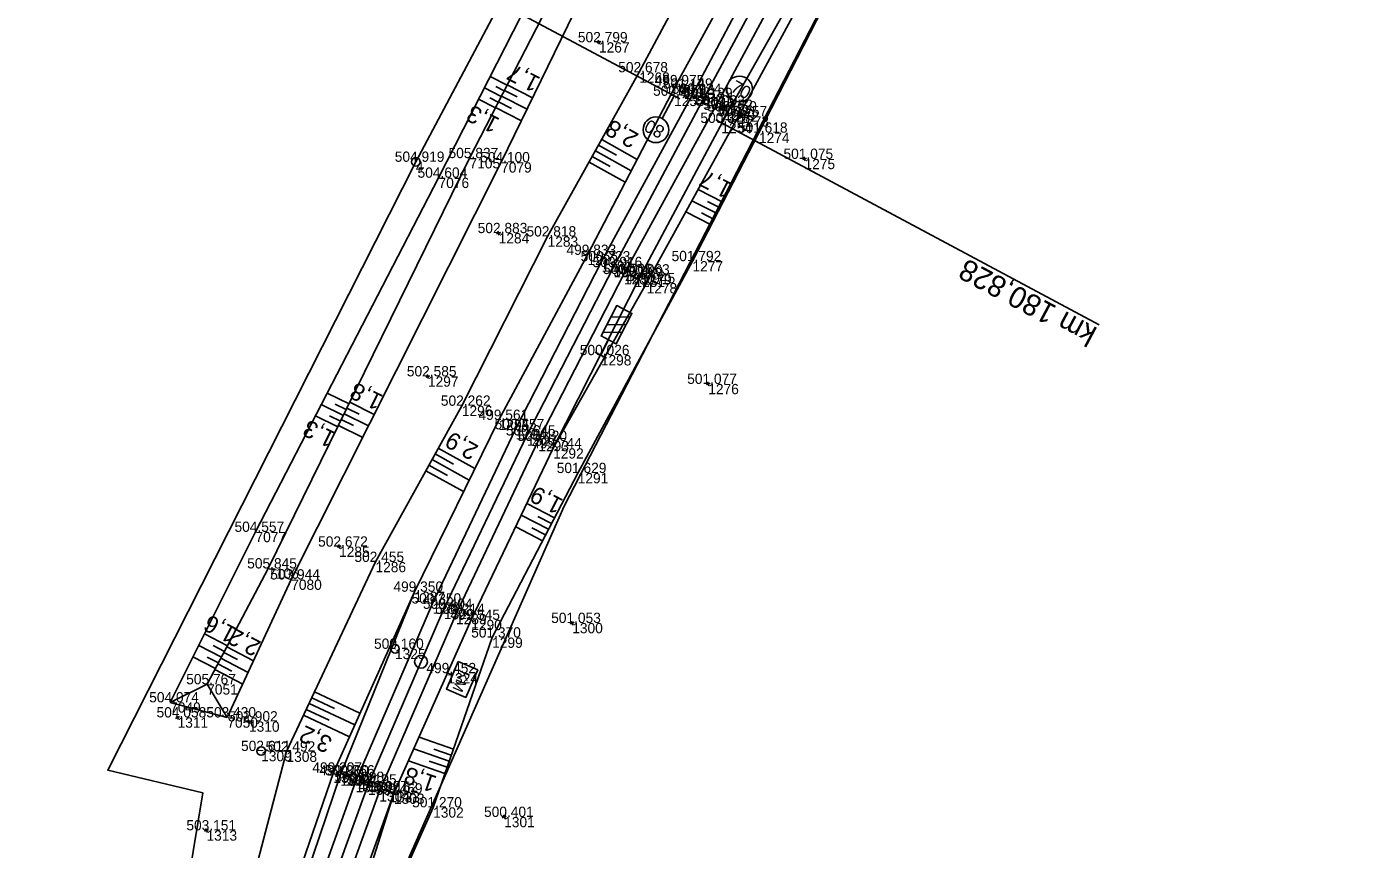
# Model space of a CAD drawing. Extents: x -1234191 to 23050, y -1290331 to -741191.
# Drawn here: x -865301.6 to -865146.4, y -1106697.5 to -1106601.4 of the extents above; entities that cross this region are included whole.
import ezdxf

# ---------------------------------------------------------------- set-up
doc = ezdxf.new("R2010")
doc.units = 0
for name, color, linetype in [('Vrstva 1', 7, 'Continuous'), ('Vrstva 36', 7, 'Continuous'), ('Vrstva 4', 7, 'Continuous'), ('Vrstva 48', 7, 'Continuous'), ('Vrstva 49', 7, 'Continuous'), ('Vrstva 5', 7, 'Continuous'), ('Vrstva 53', 7, 'Continuous'), ('Vrstva 60', 7, 'Continuous'), ('Vrstva 61', 7, 'Continuous'), ('Vrstva 7', 7, 'Continuous')]:
    doc.layers.add(name, color=color, linetype=linetype)

msp = doc.modelspace()

# ---------------------------------------------------------------- linework, layer by layer
at = {"layer": 'Vrstva 1'}
msp.add_lwpolyline([(-865141.69, -1106364.63), (-865143.95, -1106381.71), (-865145.66, -1106393.41), (-865148.04, -1106408.08), (-865150.72, -1106422.78), (-865152.79, -1106432.88), (-865153.15, -1106434.57), (-865154.41, -1106440.23), (-865157.38, -1106452.54), (-865157.84, -1106454.35), (-865160.08, -1106462.78), (-865167.31, -1106487.12), (-865175.71, -1106511.24), (-865184.94, -1106534.46), (-865195.11, -1106557.05), (-865201.68, -1106570.42), (-865208.41, -1106583.47), (-865215.48, -1106596.78), (-865222.49, -1106609.8), (-865233.04, -1106629.54), (-865243.15, -1106649.2), (-865252.85, -1106669.45), (-865261.7, -1106689.97), (-865270.22, -1106713.53)], dxfattribs=at)
at = {"layer": 'Vrstva 36'}
msp.add_circle((-865274.18, -1106686.05), 0.5, dxfattribs=at)
at = {"layer": 'Vrstva 4'}
for points in [[(-865156.65, -1106438.86), (-865159.94, -1106453.93), (-865161.87, -1106460.79), (-865162.62, -1106463.65), (-865170.75, -1106485.95), (-865178.84, -1106509.9), (-865188.13, -1106532.81), (-865198.22, -1106555.55), (-865204.97, -1106568.82), (-865211.89, -1106582.03), (-865218.58, -1106595.15), (-865225.78, -1106608.29), (-865236.08, -1106628.11), (-865246.44, -1106647.38), (-865256.29, -1106667.45), (-865264.95, -1106688.91), (-865272.84, -1106712.23)], [(-865271.61, -1106713.21), (-865263.16, -1106689.66), (-865254.18, -1106668.83), (-865244.48, -1106648.47), (-865234.43, -1106628.87), (-865223.78, -1106609.3), (-865216.77, -1106596.03), (-865209.79, -1106582.88), (-865202.97, -1106569.9), (-865196.43, -1106556.41), (-865186.34, -1106533.85), (-865176.98, -1106510.42), (-865168.84, -1106486.64), (-865162.62, -1106463.66)], [(-865158.06, -1106465.61), (-865165.98, -1106487.56), (-865174.29, -1106511.52), (-865183.57, -1106534.98), (-865193.8, -1106557.58), (-865200.21, -1106571), (-865207.07, -1106584.39), (-865214.01, -1106597.53), (-865221.06, -1106610.67), (-865231.82, -1106630.35), (-865241.82, -1106649.84), (-865251.43, -1106670.04), (-865260.38, -1106690.75), (-865268.8, -1106714.12)], [(-865267.2, -1106714.69), (-865258.68, -1106691.02), (-865249.65, -1106670.73), (-865240.09, -1106650.7), (-865229.83, -1106630.4), (-865219.65, -1106611.36), (-865212.34, -1106598.41), (-865205.78, -1106585.16), (-865199.04, -1106571.62), (-865192.16, -1106557.8), (-865182, -1106535.68), (-865172.94, -1106511.93), (-865164.71, -1106488.15), (-865158.06, -1106465.61)]]:
    msp.add_lwpolyline(points, dxfattribs=at)
at = {"layer": 'Vrstva 48'}
for p, q in [((-865246.14, -1106609.61), (-865248.11, -1106608.6)), ((-865245.46, -1106608.28), (-865247.43, -1106607.26)), ((-865245.8, -1106608.95), (-865246.79, -1106608.44)), ((-865245.44, -1106608.24), (-865242.49, -1106609.76)), ((-865246.83, -1106610.95), (-865248.79, -1106609.93)), ((-865246.49, -1106610.28), (-865247.47, -1106609.77)), ((-865246.12, -1106609.58), (-865243.14, -1106611.11)), ((-865245.78, -1106608.91), (-865244.3, -1106609.67)), ((-865246.81, -1106610.91), (-865243.8, -1106612.46)), ((-865246.47, -1106610.24), (-865244.97, -1106611.01)), ((-865234.42, -1106614.65), (-865230.29, -1106616.96)), ((-865235.16, -1106615.96), (-865230.98, -1106618.29)), ((-865234.79, -1106615.3), (-865232.71, -1106616.46)), ((-865235.89, -1106617.27), (-865231.67, -1106619.62)), ((-865235.52, -1106616.61), (-865233.42, -1106617.78)), ((-865220.26, -1106621.96), (-865223.15, -1106620.46)), ((-865220.95, -1106623.29), (-865223.88, -1106621.78)), ((-865220.6, -1106622.62), (-865222.06, -1106621.87)), ((-865221.64, -1106624.62), (-865224.6, -1106623.09)), ((-865221.29, -1106623.96), (-865222.77, -1106623.19)), ((-865263.92, -1106645.5), (-865266.47, -1106644.26)), ((-865264.58, -1106646.85), (-865267.16, -1106645.59)), ((-865264.25, -1106646.18), (-865265.53, -1106645.55)), ((-865263.84, -1106645.33), (-865260.97, -1106646.74)), ((-865265.24, -1106648.2), (-865267.84, -1106646.92)), ((-865264.91, -1106647.52), (-865266.21, -1106646.89)), ((-865264.83, -1106647.35), (-865263.4, -1106648.05)), ((-865264.5, -1106646.68), (-865261.64, -1106648.08)), ((-865264.17, -1106646), (-865262.74, -1106646.71)), ((-865265.16, -1106648.02), (-865262.32, -1106649.42)), ((-865254.23, -1106652.01), (-865249.89, -1106654.41)), ((-865253.86, -1106651.36), (-865251.71, -1106652.55)), ((-865253.5, -1106650.7), (-865249.23, -1106653.06)), ((-865254.95, -1106653.33), (-865250.55, -1106655.76)), ((-865254.59, -1106652.67), (-865252.41, -1106653.88)), ((-865239.94, -1106658.82), (-865243.17, -1106657.15)), ((-865240.64, -1106660.15), (-865243.81, -1106658.5)), ((-865240.29, -1106659.49), (-865241.89, -1106658.66)), ((-865241.33, -1106661.49), (-865244.46, -1106659.86)), ((-865240.98, -1106660.82), (-865242.56, -1106660)), ((-865278.82, -1106675.11), (-865281.47, -1106673.71)), ((-865278.12, -1106673.78), (-865280.8, -1106672.37)), ((-865278.47, -1106674.44), (-865279.8, -1106673.74)), ((-865279.52, -1106676.43), (-865282.14, -1106675.05)), ((-865279.17, -1106675.77), (-865280.48, -1106675.08)), ((-865278.88, -1106675.22), (-865275.7, -1106676.89)), ((-865278.53, -1106674.56), (-865276.96, -1106675.38)), ((-865278.18, -1106673.89), (-865275.07, -1106675.53)), ((-865279.57, -1106676.55), (-865276.33, -1106678.25)), ((-865279.23, -1106675.88), (-865277.62, -1106676.73)), ((-865268.27, -1106679.83), (-865265.61, -1106681.07)), ((-865267.95, -1106679.15), (-865262.64, -1106681.64)), ((-865268.91, -1106681.19), (-865266.23, -1106682.44)), ((-865268.59, -1106680.51), (-865263.26, -1106683.01)), ((-865269.22, -1106681.86), (-865263.87, -1106684.38)), ((-865251.74, -1106685.83), (-865255.75, -1106684.43)), ((-865252.23, -1106687.24), (-865256.36, -1106685.81)), ((-865251.98, -1106686.53), (-865254.02, -1106685.83)), ((-865252.72, -1106688.66), (-865256.97, -1106687.18)), ((-865252.48, -1106687.95), (-865254.57, -1106687.22))]:
    msp.add_line(p, q, dxfattribs=at)
at = {"layer": 'Vrstva 49'}
for p, q in [((-865234.5, -1106603.2), (-865234.98, -1106603.35)), ((-865234.82, -1106603.04), (-865234.67, -1106603.52)), ((-865210.5, -1106616.83), (-865210.98, -1106616.97)), ((-865210.81, -1106616.66), (-865210.67, -1106617.14)), ((-865246.21, -1106625.5), (-865246.69, -1106625.65)), ((-865246.53, -1106625.33), (-865246.38, -1106625.81)), ((-865254.47, -1106642.23), (-865254.95, -1106642.38)), ((-865254.79, -1106642.07), (-865254.63, -1106642.54)), ((-865221.75, -1106643.1), (-865222.22, -1106643.25)), ((-865222.06, -1106642.94), (-865221.91, -1106643.41)), ((-865264.84, -1106662.1), (-865265.31, -1106662.26)), ((-865265.16, -1106661.95), (-865265, -1106662.42)), ((-865237.63, -1106671.02), (-865238.1, -1106671.19)), ((-865237.95, -1106670.87), (-865237.78, -1106671.34)), ((-865283.71, -1106682.03), (-865284.17, -1106682.24)), ((-865284.05, -1106681.91), (-865283.83, -1106682.36)), ((-865275.37, -1106682.51), (-865275.84, -1106682.7)), ((-865275.7, -1106682.37), (-865275.51, -1106682.84)), ((-865245.57, -1106693.66), (-865246.04, -1106693.84)), ((-865245.9, -1106693.52), (-865245.71, -1106693.98)), ((-865280.33, -1106695.22), (-865280.78, -1106695.43)), ((-865280.66, -1106695.1), (-865280.45, -1106695.55))]:
    msp.add_line(p, q, dxfattribs=at)
for points in [[(-865273.87, -1106712.18), (-865265.74, -1106688.57), (-865256.29, -1106667.45), (-865246.44, -1106647.38), (-865236.08, -1106628.11), (-865225.78, -1106608.29), (-865218.58, -1106595.15), (-865211.89, -1106582.03), (-865204.97, -1106568.82), (-865198.22, -1106555.55), (-865188.13, -1106532.81), (-865178.84, -1106509.9), (-865170.75, -1106485.95), (-865164.54, -1106464.38), (-865164.85, -1106464.24), (-865163.93, -1106461.54), (-865163, -1106456.61), (-865162.58, -1106456.56), (-865161.66, -1106454.33), (-865161.99, -1106456.02), (-865161.63, -1106456.28), (-865162.24, -1106460.7)], [(-865264.56, -1106716.17), (-865254.1, -1106692.63), (-865247.21, -1106672.8), (-865237.22, -1106653.59), (-865223.82, -1106628.84), (-865216.06, -1106613.84), (-865208.6, -1106599.29), (-865202.09, -1106586.89), (-865196.2, -1106572.75), (-865189.54, -1106559.17), (-865179.71, -1106538.07), (-865170.26, -1106513.43), (-865162.16, -1106489.67), (-865154.67, -1106465.04), (-865156.45, -1106464.44)], [(-865297.8, -1106910.95), (-865301.49, -1106884.83), (-865301.57, -1106862.3), (-865300.66, -1106837.39), (-865298.37, -1106810.16), (-865294.53, -1106785.6), (-865287.98, -1106760.27), (-865282.97, -1106736.07), (-865277.68, -1106710.81), (-865271.22, -1106686.12), (-865260.83, -1106663.97), (-865250.75, -1106645.73), (-865240.74, -1106625.96), (-865230.04, -1106606.79), (-865221.82, -1106591.38), (-865215.71, -1106580.01), (-865206.84, -1106567.4), (-865200.8, -1106554.97), (-865189.9, -1106532.43), (-865180.71, -1106509.04), (-865172.12, -1106485.47)], [(-865281.81, -1106787.37), (-865277.56, -1106762.77), (-865273.36, -1106738.48), (-865266.23, -1106714.94), (-865258.68, -1106691.02), (-865249.65, -1106670.73), (-865240.09, -1106650.7), (-865229.18, -1106631.42), (-865218.45, -1106611.92), (-865211.42, -1106598.95), (-865204.65, -1106585.73), (-865197.61, -1106572.48), (-865191.07, -1106558.81), (-865180.7, -1106536.08), (-865170.26, -1106513.43)], [(-865227.86, -1106573.65), (-865232.25, -1106582.63), (-865249.85, -1106616.81), (-865273.35, -1106664.73), (-865280.48, -1106678.26)], [(-865225.32, -1106575.2), (-865229.76, -1106583.63), (-865246.16, -1106617.3), (-865270.67, -1106666.02), (-865278.13, -1106682.13)], [(-865237.93, -1106588.65), (-865253.47, -1106619.1), (-865274.84, -1106660.46), (-865284.8, -1106680.37)], [(-865284.8, -1106680.37), (-865280.48, -1106678.26), (-865278.13, -1106682.13)], [(-865284.8, -1106680.37), (-865278.13, -1106682.13)]]:
    msp.add_lwpolyline(points, dxfattribs=at)
at = {"layer": 'Vrstva 5'}
for p, q in [((-865270.06, -1106585.97), (-865225.97, -1106609.53)), ((-865225.97, -1106609.53), (-865227.38, -1106612.18)), ((-865225.3, -1106609.89), (-865226.63, -1106609.18)), ((-865220.45, -1106612.7), (-865219.04, -1106610.06)), ((-865221.11, -1106612.35), (-865219.79, -1106613.05)), ((-865176.35, -1106636.27), (-865220.45, -1106612.7))]:
    msp.add_line(p, q, dxfattribs=at)
for centre in [(-865218.33, -1106608.73), (-865228.09, -1106613.5)]:
    msp.add_circle(centre, 1.5, dxfattribs=at)
at = {"layer": 'Vrstva 53'}
msp.add_line((-865256.18, -1106617.24), (-865256.08, -1106617.24), dxfattribs=at)
for points in [[(-865227.66, -1105917.88), (-865232.36, -1105922.35), (-865183.09, -1106010.41), (-865167.99, -1106045.38), (-865144.78, -1106101.17), (-865131.99, -1106166.39), (-865125.85, -1106219.01), (-865125.39, -1106238.65), (-865125.96, -1106278.9), (-865132.87, -1106334.65), (-865136.85, -1106381.38), (-865151.63, -1106445.1), (-865163.44, -1106490.83), (-865178.82, -1106535.04), (-865200.93, -1106584.09), (-865238.82, -1106657.44), (-865256.95, -1106698.52)], [(-865292.28, -1106759.44), (-865281, -1106690.92), (-865292.09, -1106688.29), (-865256.12, -1106617.24), (-865192.39, -1106497.22), (-865182.07, -1106466.18), (-865172.59, -1106441.08), (-865160.97, -1106443.62), (-865159.33, -1106435.02), (-865146.44, -1106359.55), (-865157.51, -1106356.95), (-865157, -1106331.91), (-865151.9, -1106265.92), (-865152.14, -1106213.17), (-865160.59, -1106155.82), (-865173.12, -1106100.65), (-865192.84, -1106055.27), (-865212.4, -1106009.43), (-865251.57, -1105941.08), (-865241.97, -1105927.13)]]:
    msp.add_lwpolyline(points, dxfattribs=at)
msp.add_circle((-865256.12, -1106617.24), 0.499, dxfattribs=at)
at = {"layer": 'Vrstva 60'}
for p, q in [((-865234.74, -1106603.28), (-865234.74, -1106603.28)), ((-865230.04, -1106606.79), (-865230.04, -1106606.79)), ((-865225.78, -1106608.29), (-865225.78, -1106608.29)), ((-865225.97, -1106609.53), (-865225.97, -1106609.53)), ((-865224.81, -1106608.7), (-865224.81, -1106608.7)), ((-865223.78, -1106609.3), (-865223.78, -1106609.3)), ((-865222.49, -1106609.8), (-865222.49, -1106609.8)), ((-865221.06, -1106610.67), (-865221.06, -1106610.67)), ((-865220.12, -1106611.18), (-865220.12, -1106611.18)), ((-865219.65, -1106611.36), (-865219.65, -1106611.36)), ((-865220.45, -1106612.7), (-865220.45, -1106612.7)), ((-865218.45, -1106611.92), (-865218.45, -1106611.92)), ((-865216.06, -1106613.84), (-865216.06, -1106613.84)), ((-865256.12, -1106617.24), (-865256.12, -1106617.24)), ((-865249.85, -1106616.81), (-865249.85, -1106616.81)), ((-865246.16, -1106617.3), (-865246.16, -1106617.3)), ((-865210.74, -1106616.9), (-865210.74, -1106616.9)), ((-865253.47, -1106619.1), (-865253.47, -1106619.1)), ((-865246.45, -1106625.57), (-865246.45, -1106625.57)), ((-865240.74, -1106625.96), (-865240.74, -1106625.96)), ((-865236.08, -1106628.11), (-865236.08, -1106628.11)), ((-865234.43, -1106628.87), (-865234.43, -1106628.87)), ((-865233.04, -1106629.54), (-865233.04, -1106629.54)), ((-865231.82, -1106630.35), (-865231.82, -1106630.35)), ((-865223.82, -1106628.84), (-865223.82, -1106628.84)), ((-865230.59, -1106630.66), (-865230.59, -1106630.66)), ((-865229.83, -1106630.4), (-865229.83, -1106630.4)), ((-865229.18, -1106631.42), (-865229.18, -1106631.42)), ((-865234.52, -1106639.82), (-865234.52, -1106639.82)), ((-865254.71, -1106642.3), (-865254.71, -1106642.3)), ((-865221.98, -1106643.18), (-865221.98, -1106643.18)), ((-865250.75, -1106645.73), (-865250.75, -1106645.73)), ((-865246.44, -1106647.38), (-865246.44, -1106647.38)), ((-865244.48, -1106648.47), (-865244.48, -1106648.47)), ((-865243.15, -1106649.2), (-865243.15, -1106649.2)), ((-865241.82, -1106649.84), (-865241.82, -1106649.84)), ((-865240.09, -1106650.7), (-865240.09, -1106650.7)), ((-865237.22, -1106653.59), (-865237.22, -1106653.59)), ((-865274.84, -1106660.46), (-865274.84, -1106660.46)), ((-865265.08, -1106662.18), (-865265.08, -1106662.18)), ((-865260.83, -1106663.97), (-865260.83, -1106663.97)), ((-865273.35, -1106664.73), (-865273.35, -1106664.73)), ((-865270.67, -1106666.02), (-865270.67, -1106666.02)), ((-865256.29, -1106667.45), (-865256.29, -1106667.45)), ((-865254.18, -1106668.83), (-865254.18, -1106668.83)), ((-865252.85, -1106669.45), (-865252.85, -1106669.45)), ((-865251.43, -1106670.04), (-865251.43, -1106670.04)), ((-865249.65, -1106670.73), (-865249.65, -1106670.73)), ((-865237.86, -1106671.1), (-865237.86, -1106671.1)), ((-865247.21, -1106672.8), (-865247.21, -1106672.8)), ((-865258.55, -1106674.12), (-865258.55, -1106674.12)), ((-865280.48, -1106678.26), (-865280.48, -1106678.26)), ((-865252.44, -1106676.96), (-865252.44, -1106676.96)), ((-865284.8, -1106680.37), (-865284.8, -1106680.37)), ((-865283.94, -1106682.13), (-865283.94, -1106682.13)), ((-865278.13, -1106682.13), (-865278.13, -1106682.13)), ((-865275.6, -1106682.6), (-865275.6, -1106682.6)), ((-865274.18, -1106686.05), (-865274.18, -1106686.05)), ((-865271.22, -1106686.12), (-865271.22, -1106686.12)), ((-865265.74, -1106688.57), (-865265.74, -1106688.57)), ((-865264.95, -1106688.91), (-865264.95, -1106688.91)), ((-865264.28, -1106688.9), (-865264.28, -1106688.9)), ((-865263.16, -1106689.66), (-865263.16, -1106689.66)), ((-865261.7, -1106689.97), (-865261.7, -1106689.97)), ((-865260.38, -1106690.75), (-865260.38, -1106690.75)), ((-865259.21, -1106690.83), (-865259.21, -1106690.83)), ((-865258.68, -1106691.02), (-865258.68, -1106691.02)), ((-865254.1, -1106692.63), (-865254.1, -1106692.63)), ((-865245.81, -1106693.75), (-865245.81, -1106693.75)), ((-865280.56, -1106695.32), (-865280.56, -1106695.32))]:
    msp.add_line(p, q, dxfattribs=at)
at = {"layer": 'Vrstva 7'}
for p, q in [((-865224.37, -1106608.93), (-865225.25, -1106608.46)), ((-865224.58, -1106608.26), (-865225.05, -1106609.14)), ((-865219.68, -1106611.42), (-865220.56, -1106610.95)), ((-865219.89, -1106610.74), (-865220.36, -1106611.62)), ((-865230.35, -1106630.22), (-865230.82, -1106631.1)), ((-865230.15, -1106630.9), (-865231.03, -1106630.43)), ((-865231.58, -1106636.28), (-865233.81, -1106636.25)), ((-865233.36, -1106635.36), (-865231.12, -1106635.39)), ((-865234.27, -1106637.14), (-865232.03, -1106637.16)), ((-865235.19, -1106639.48), (-865233.86, -1106640.16)), ((-865258.53, -1106674.08), (-865258.57, -1106674.17)), ((-865252.44, -1106676.96), (-865251.87, -1106677.21)), ((-865263.81, -1106689.07), (-865264.75, -1106688.72)), ((-865264.11, -1106688.42), (-865264.45, -1106689.37)), ((-865258.76, -1106691.02), (-865259.67, -1106690.63)), ((-865259.02, -1106690.37), (-865259.41, -1106691.29))]:
    msp.add_line(p, q, dxfattribs=at)
msp.add_lwpolyline([(-865234.52, -1106639.82), (-865233.61, -1106638.04), (-865232.72, -1106638.5), (-865230.89, -1106634.94), (-865232.67, -1106634.03), (-865234.5, -1106637.58), (-865233.61, -1106638.04)], dxfattribs=at)
msp.add_lwpolyline([(-865251.18, -1106675.61), (-865248.9, -1106676.59), (-865250.28, -1106679.79), (-865252.56, -1106678.81)], close=True, dxfattribs=at)
for centre, radius in [((-865258.55, -1106674.12), 0.5), ((-865255.52, -1106675.63), 0.75)]:
    msp.add_circle(centre, radius, dxfattribs=at)

# ---------------------------------------------------------------- texts
at = {"layer": 'Vrstva 48'}
for s, rotation, p in [('1,7', 152.7604, (-865241.46, -1106607.45)), ('1,3', 152.7604, (-865246.2, -1106612.24)), ('2,8', 150.8085, (-865229.97, -1106614.03)), ('1,7', 152.6793, (-865218.98, -1106619.86)), ('1,8', 153.8742, (-865259.81, -1106644.57)), ('1,3', 153.8742, (-865265.3, -1106648.94)), ('2,9', 151.0786, (-865248.68, -1106650.45)), ('1,9', 152.5285, (-865238.78, -1106656.74)), ('1,6', 152.2263, (-865276.88, -1106671.8)), ('2,2', 152.2263, (-865274.07, -1106673.34)), ('3,2', 154.8785, (-865265.72, -1106684.57)), ('1,8', 160.8322, (-865253.54, -1106689.06))]:
    msp.add_text(s, height=2, rotation=rotation, dxfattribs=at).set_placement(p)
at = {"layer": 'Vrstva 5'}
for s, height, rotation, p in [('70', 1.5, 331.8765, (-865219.49, -1106608.96)), ('80', 1.5, 151.8765, (-865226.93, -1106613.27)), ('km 180,828', 2.5, 151.8765, (-865176.41, -1106636.71))]:
    msp.add_text(s, height=height, rotation=rotation, dxfattribs=at).set_placement(p)
at = {"layer": 'Vrstva 60'}
for s, p in [('1267', (-865234.74, -1106604.48)), ('1268', (-865230.04, -1106608)), ('1269', (-865225.78, -1106609.49)), ('1255', (-865225.97, -1106610.73)), ('1250', (-865224.81, -1106609.9)), ('1270', (-865223.78, -1106610.5)), ('1246', (-865222.49, -1106611)), ('1271', (-865221.06, -1106611.87)), ('1249', (-865220.12, -1106612.38)), ('1272', (-865219.65, -1106612.56)), ('1254', (-865220.45, -1106613.9)), ('1273', (-865218.45, -1106613.12)), ('1274', (-865216.06, -1106615.04)), ('4', (-865256.12, -1106618.44)), ('7105', (-865249.85, -1106618.01)), ('7079', (-865246.16, -1106618.5)), ('1275', (-865210.74, -1106618.1)), ('7076', (-865253.47, -1106620.3)), ('1284', (-865246.45, -1106626.77)), ('1283', (-865240.74, -1106627.16)), ('1282', (-865236.08, -1106629.31)), ('1281', (-865234.43, -1106630.07)), ('1252', (-865233.04, -1106630.74)), ('1280', (-865231.82, -1106631.55)), ('1277', (-865223.82, -1106630.04)), ('1251', (-865230.59, -1106631.86)), ('1279', (-865229.83, -1106631.6)), ('1278', (-865229.18, -1106632.61)), ('1298', (-865234.52, -1106641.02)), ('1297', (-865254.71, -1106643.5)), ('1276', (-865221.98, -1106644.38)), ('1296', (-865250.75, -1106646.93)), ('1295', (-865246.44, -1106648.58)), ('1294', (-865244.48, -1106649.67)), ('1327', (-865243.15, -1106650.4)), ('1293', (-865241.82, -1106651.04)), ('1292', (-865240.09, -1106651.9)), ('1291', (-865237.22, -1106654.79)), ('7077', (-865274.84, -1106661.66)), ('1285', (-865265.08, -1106663.38)), ('1286', (-865260.83, -1106665.17)), ('7106', (-865273.35, -1106665.93)), ('7080', (-865270.67, -1106667.23)), ('1287', (-865256.29, -1106668.65)), ('1288', (-865254.18, -1106670.03)), ('1329', (-865252.85, -1106670.65)), ('1289', (-865251.43, -1106671.24)), ('1290', (-865249.65, -1106671.93)), ('1300', (-865237.86, -1106672.3)), ('1299', (-865247.21, -1106674)), ('1325', (-865258.55, -1106675.32)), ('7051', (-865280.48, -1106679.46)), ('1324', (-865252.44, -1106678.16)), ('7049', (-865284.8, -1106681.57)), ('1311', (-865283.94, -1106683.33)), ('7050', (-865278.13, -1106683.33)), ('1310', (-865275.6, -1106683.8)), ('1309', (-865274.18, -1106687.25)), ('1308', (-865271.22, -1106687.32)), ('1307', (-865265.74, -1106689.77)), ('1306', (-865264.95, -1106690.11)), ('1334', (-865264.28, -1106690.09)), ('1305', (-865263.16, -1106690.86)), ('1331', (-865261.7, -1106691.17)), ('1304', (-865260.38, -1106691.95)), ('1333', (-865259.21, -1106692.03)), ('1303', (-865258.68, -1106692.22)), ('1302', (-865254.1, -1106693.83)), ('1301', (-865245.81, -1106694.95)), ('1313', (-865280.56, -1106696.52))]:
    msp.add_text(s, height=1.2, dxfattribs=at).set_placement(p)
at = {"layer": 'Vrstva 61'}
for s, p in [('502.799', (-865237.2, -1106603.28)), ('502.678', (-865232.49, -1106606.79)), ('499.975', (-865228.24, -1106608.29)), ('500.284', (-865228.42, -1106609.53)), ('501.149', (-865227.27, -1106608.7)), ('500.924', (-865226.23, -1106609.3)), ('501.189', (-865224.94, -1106609.8)), ('501.002', (-865223.51, -1106610.67)), ('501.152', (-865222.57, -1106611.18)), ('500.359', (-865222.1, -1106611.36)), ('500.378', (-865222.9, -1106612.7)), ('500.257', (-865220.9, -1106611.92)), ('501.618', (-865218.52, -1106613.84)), ('504.919', (-865258.58, -1106617.24)), ('505.837', (-865252.3, -1106616.81)), ('504.100', (-865248.61, -1106617.3)), ('501.075', (-865213.2, -1106616.9)), ('504.604', (-865255.92, -1106619.1)), ('502.883', (-865248.9, -1106625.57)), ('502.818', (-865243.2, -1106625.96)), ('499.833', (-865238.53, -1106628.11)), ('500.723', (-865236.88, -1106628.87)), ('500.916', (-865235.49, -1106629.54)), ('501.792', (-865226.26, -1106628.84)), ('500.706', (-865234.27, -1106630.35)), ('500.869', (-865233.04, -1106630.66)), ('500.063', (-865232.28, -1106630.4)), ('499.945', (-865231.64, -1106631.42)), ('500.026', (-865236.98, -1106639.82)), ('502.585', (-865257.17, -1106642.3)), ('501.077', (-865224.44, -1106643.18)), ('502.262', (-865253.2, -1106645.73)), ('499.561', (-865248.8, -1106647.38)), ('500.457', (-865246.93, -1106648.47)), ('500.645', (-865245.61, -1106649.2)), ('500.420', (-865244.27, -1106649.84)), ('499.744', (-865242.54, -1106650.7)), ('501.629', (-865239.67, -1106653.59)), ('504.557', (-865277.29, -1106660.46)), ('502.672', (-865267.53, -1106662.18)), ('502.455', (-865263.29, -1106663.97)), ('505.845', (-865275.81, -1106664.73)), ('503.944', (-865273.12, -1106666.02)), ('499.350', (-865258.74, -1106667.45)), ('500.350', (-865256.63, -1106668.83)), ('500.404', (-865255.3, -1106669.45)), ('500.214', (-865253.88, -1106670.04)), ('499.545', (-865252.1, -1106670.73)), ('501.053', (-865240.32, -1106671.1)), ('501.370', (-865249.66, -1106672.8)), ('500.160', (-865261, -1106674.12)), ('499.452', (-865254.89, -1106676.96)), ('505.767', (-865282.93, -1106678.26)), ('504.074', (-865287.25, -1106680.37)), ('504.058', (-865286.39, -1106682.13)), ('503.430', (-865280.58, -1106682.13)), ('502.902', (-865278.05, -1106682.6)), ('502.611', (-865276.53, -1106686.05)), ('502.492', (-865273.67, -1106686.12)), ('499.207', (-865268.2, -1106688.57)), ('499.360', (-865267.4, -1106688.91)), ('500.266', (-865266.73, -1106688.9)), ('500.098', (-865265.62, -1106689.66)), ('500.195', (-865264.16, -1106689.97)), ('499.957', (-865262.83, -1106690.75)), ('500.152', (-865261.66, -1106690.83)), ('499.469', (-865261.14, -1106691.02)), ('501.270', (-865256.55, -1106692.63)), ('500.401', (-865248.16, -1106693.75)), ('503.151', (-865282.91, -1106695.32))]:
    msp.add_text(s, height=1.2, dxfattribs=at).set_placement(p)
at = {"layer": 'Vrstva 7'}
msp.add_text('KM', height=1.247, rotation=246.6812, dxfattribs=at).set_placement((-865250.89, -1106676.52))

doc.saveas('drawing.dxf')
